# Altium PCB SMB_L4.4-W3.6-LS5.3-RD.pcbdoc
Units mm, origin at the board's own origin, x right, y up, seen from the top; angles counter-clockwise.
Board outline 19.5 x 16.36 mm, 2 copper layers (Top Layer, Bottom Layer), stack 0 mm thick; 1 components, 0 nets, 2 pads, 0 vias.
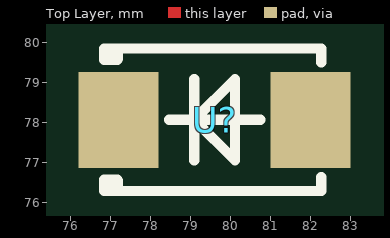
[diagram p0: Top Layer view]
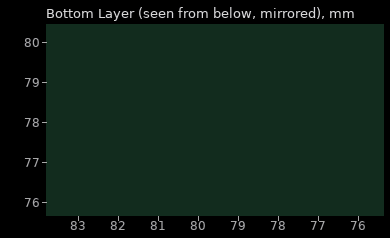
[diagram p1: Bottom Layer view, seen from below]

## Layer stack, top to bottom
Top Layer: signal copper (thickness not stored)
Bottom Layer: signal copper (thickness not stored)

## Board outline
89.35,69.85 69.85,69.85 69.85,86.21 89.35,86.21

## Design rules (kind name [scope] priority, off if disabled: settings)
PasteMaskExpansion "Paste Mask Expansion" [All] p1: expansion=0
SolderMaskExpansion "Solder Mask Expansion" [IsVia] p1: expansion=-25.4 istentingtop=TRUE
SolderMaskExpansion "Solder Mask Expansion" [All] p2: expansion=0.051 istentingtop=FALSE

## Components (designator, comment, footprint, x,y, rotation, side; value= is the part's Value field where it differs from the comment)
U? "" SMB_L4.4-W3.6-LS5.3-RD 79.6,78.06 r0 top

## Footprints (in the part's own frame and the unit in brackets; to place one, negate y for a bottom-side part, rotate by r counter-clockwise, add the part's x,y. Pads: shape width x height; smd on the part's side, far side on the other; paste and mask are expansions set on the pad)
SMB_L4.4-W3.6-LS5.3-RD [mm]
  rect 2x2.4 smd: 1(-2.4,0) 2(2.4,0)
  silkscreen extent -2.76,-1.78 2.67,1.78

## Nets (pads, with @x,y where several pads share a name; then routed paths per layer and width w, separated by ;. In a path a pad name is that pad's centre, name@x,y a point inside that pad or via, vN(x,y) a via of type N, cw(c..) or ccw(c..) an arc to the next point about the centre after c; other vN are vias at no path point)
pads on no net: U?.1 U?.2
